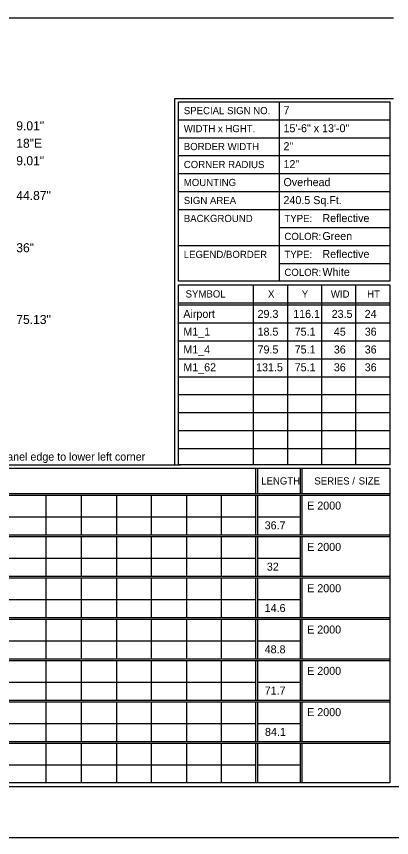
# Model space of a CAD drawing. Extents: x 2149934 to 2150188, y 145114 to 145238.
# Drawn here: x 2150052 to 2150076.2, y 145114.1 to 145167.1 of the extents above; entities that cross this region are included whole.
import ezdxf

# ---------------------------------------------------------------- set-up
doc = ezdxf.new("R2010")
doc.units = 0
for name, color, linetype in [('BORDER', 7, 'Continuous'), ('GSDIMS', 7, 'Continuous'), ('GSSHT', 7, 'Continuous'), ('Level 1', 7, 'Continuous'), ('PDF', 7, 'Continuous')]:
    doc.layers.add(name, color=color, linetype=linetype)

msp = doc.modelspace()

# ---------------------------------------------------------------- linework, layer by layer
at = {"layer": 'BORDER'}
for p, q in [((2150017.557, 145117.388), (2150171.536, 145117.388)), ((2150010.458, 145114.088), (2150174.061, 145114.088))]:
    msp.add_line(p, q, dxfattribs=at)
at = {"layer": 'Level 1'}
for p, q in [((2150076.316, 145166.95), (2150017.557, 145166.95)), ((2150062.21, 145161.778), (2150076.316, 145161.778)), ((2150068.935, 145161.546), (2150068.935, 145149.975)), ((2150062.442, 145160.387), (2150076.084, 145160.387)), ((2150062.442, 145159.227), (2150076.084, 145159.227)), ((2150062.442, 145158.091), (2150076.084, 145158.091)), ((2150062.442, 145156.932), (2150076.084, 145156.932)), ((2150062.442, 145155.772), (2150076.084, 145155.772)), ((2150062.442, 145154.613), (2150076.084, 145154.613)), ((2150068.935, 145153.453), (2150076.084, 145153.453)), ((2150062.442, 145152.294), (2150076.084, 145152.294)), ((2150068.935, 145151.134), (2150076.084, 145151.134)), ((2150062.442, 145138.143), (2150062.442, 145149.743)), ((2150062.442, 145149.743), (2150076.084, 145149.743)), ((2150067.272, 145149.737), (2150067.272, 145148.578)), ((2150069.475, 145149.737), (2150069.475, 145148.578)), ((2150071.678, 145149.737), (2150071.678, 145148.578)), ((2150073.881, 145149.737), (2150073.881, 145148.578)), ((2150076.084, 145149.743), (2150076.084, 145138.143)), ((2150062.442, 145148.578), (2150076.084, 145148.578)), ((2150062.442, 145148.462), (2150076.084, 145148.462)), ((2150067.272, 145148.578), (2150067.272, 145138.143)), ((2150069.475, 145148.578), (2150069.475, 145138.143)), ((2150071.678, 145148.578), (2150071.678, 145138.143)), ((2150073.881, 145148.578), (2150073.881, 145138.143)), ((2150062.442, 145147.303), (2150076.084, 145147.303)), ((2150062.442, 145146.143), (2150076.084, 145146.143)), ((2150062.442, 145144.984), (2150076.084, 145144.984)), ((2150062.442, 145143.824), (2150076.084, 145143.824)), ((2150062.442, 145142.665), (2150076.084, 145142.665)), ((2150062.442, 145141.505), (2150076.084, 145141.505)), ((2150062.442, 145140.346), (2150076.084, 145140.346)), ((2150062.442, 145139.186), (2150076.084, 145139.186)), ((2150017.557, 145138.143), (2150062.583, 145138.143)), ((2150076.084, 145138.143), (2150062.442, 145138.143)), ((2150067.426, 145137.911), (2150067.426, 145136.288)), ((2150067.542, 145137.911), (2150067.542, 145136.288)), ((2150070.29, 145137.911), (2150070.29, 145136.288)), ((2150070.405, 145137.911), (2150070.405, 145136.288)), ((2150017.789, 145136.288), (2150076.084, 145136.288)), ((2150017.789, 145136.172), (2150076.084, 145136.172)), ((2150053.895, 145136.172), (2150053.895, 145133.621)), ((2150056.168, 145136.172), (2150056.168, 145133.621)), ((2150058.441, 145136.172), (2150058.441, 145133.621)), ((2150060.69, 145136.172), (2150060.69, 145133.621)), ((2150062.962, 145136.172), (2150062.962, 145133.621)), ((2150065.212, 145136.172), (2150065.212, 145133.621)), ((2150067.426, 145136.172), (2150067.426, 145133.621)), ((2150067.542, 145136.172), (2150067.542, 145133.621)), ((2150070.29, 145136.172), (2150070.29, 145133.621)), ((2150070.405, 145136.172), (2150070.405, 145133.621)), ((2150017.789, 145134.78), (2150067.426, 145134.78)), ((2150067.542, 145134.78), (2150070.29, 145134.78)), ((2150017.789, 145133.621), (2150076.084, 145133.621)), ((2150017.789, 145133.505), (2150076.084, 145133.505)), ((2150053.895, 145133.505), (2150053.895, 145130.954)), ((2150056.168, 145133.505), (2150056.168, 145130.954)), ((2150058.441, 145133.505), (2150058.441, 145130.954)), ((2150060.69, 145133.505), (2150060.69, 145130.954)), ((2150062.962, 145133.505), (2150062.962, 145130.954)), ((2150065.212, 145133.505), (2150065.212, 145130.954)), ((2150067.426, 145133.505), (2150067.426, 145130.954)), ((2150067.542, 145133.505), (2150067.542, 145130.954)), ((2150070.29, 145133.505), (2150070.29, 145130.954)), ((2150070.405, 145133.505), (2150070.405, 145130.954)), ((2150017.789, 145132.113), (2150067.426, 145132.113)), ((2150067.542, 145132.113), (2150070.29, 145132.113)), ((2150017.789, 145130.954), (2150076.084, 145130.954)), ((2150017.789, 145130.838), (2150076.084, 145130.838)), ((2150053.895, 145130.838), (2150053.895, 145128.287)), ((2150056.168, 145130.838), (2150056.168, 145128.287)), ((2150058.441, 145130.838), (2150058.441, 145128.287)), ((2150060.69, 145130.838), (2150060.69, 145128.287)), ((2150062.962, 145130.838), (2150062.962, 145128.287)), ((2150065.212, 145130.838), (2150065.212, 145128.287)), ((2150067.426, 145130.838), (2150067.426, 145128.287)), ((2150067.542, 145130.838), (2150067.542, 145128.287)), ((2150070.29, 145130.838), (2150070.29, 145128.287)), ((2150070.405, 145130.838), (2150070.405, 145128.287)), ((2150017.789, 145129.447), (2150067.426, 145129.447)), ((2150067.542, 145129.447), (2150070.29, 145129.447)), ((2150017.789, 145128.287), (2150076.084, 145128.287)), ((2150017.789, 145128.171), (2150076.084, 145128.171)), ((2150053.895, 145128.171), (2150053.895, 145125.62)), ((2150056.168, 145128.171), (2150056.168, 145125.62)), ((2150058.441, 145128.171), (2150058.441, 145125.62)), ((2150060.69, 145128.171), (2150060.69, 145125.62)), ((2150062.962, 145128.171), (2150062.962, 145125.62)), ((2150065.212, 145128.171), (2150065.212, 145125.62)), ((2150067.426, 145128.171), (2150067.426, 145125.62)), ((2150067.542, 145128.171), (2150067.542, 145125.62)), ((2150070.29, 145128.171), (2150070.29, 145125.62)), ((2150070.405, 145128.171), (2150070.405, 145125.62)), ((2150017.789, 145126.78), (2150067.426, 145126.78)), ((2150067.542, 145126.78), (2150070.29, 145126.78)), ((2150017.789, 145125.62), (2150076.084, 145125.62)), ((2150017.789, 145125.504), (2150076.084, 145125.504)), ((2150053.895, 145125.504), (2150053.895, 145122.954)), ((2150056.168, 145125.504), (2150056.168, 145122.954)), ((2150058.441, 145125.504), (2150058.441, 145122.954)), ((2150060.69, 145125.504), (2150060.69, 145122.954)), ((2150062.962, 145125.504), (2150062.962, 145122.954)), ((2150065.212, 145125.504), (2150065.212, 145122.954)), ((2150067.426, 145125.504), (2150067.426, 145122.954)), ((2150067.542, 145125.504), (2150067.542, 145122.954)), ((2150070.29, 145125.504), (2150070.29, 145122.954)), ((2150070.405, 145125.504), (2150070.405, 145122.954)), ((2150017.789, 145124.113), (2150067.426, 145124.113)), ((2150067.542, 145124.113), (2150070.29, 145124.113)), ((2150017.789, 145122.954), (2150076.084, 145122.954)), ((2150017.789, 145122.838), (2150076.084, 145122.838)), ((2150053.895, 145122.838), (2150053.895, 145120.287)), ((2150056.168, 145122.838), (2150056.168, 145120.287)), ((2150058.441, 145122.838), (2150058.441, 145120.287)), ((2150060.69, 145122.838), (2150060.69, 145120.287)), ((2150062.962, 145122.838), (2150062.962, 145120.287)), ((2150065.212, 145122.838), (2150065.212, 145120.287)), ((2150067.426, 145122.838), (2150067.426, 145120.287)), ((2150067.542, 145122.838), (2150067.542, 145120.287)), ((2150070.29, 145122.838), (2150070.29, 145120.287)), ((2150070.405, 145122.838), (2150070.405, 145120.287)), ((2150017.789, 145121.446), (2150067.426, 145121.446)), ((2150067.542, 145121.446), (2150070.29, 145121.446)), ((2150017.789, 145120.287), (2150076.084, 145120.287)), ((2150017.789, 145120.171), (2150076.084, 145120.171)), ((2150053.895, 145120.171), (2150053.895, 145117.62)), ((2150056.168, 145120.171), (2150056.168, 145117.62)), ((2150058.441, 145120.171), (2150058.441, 145117.62)), ((2150060.69, 145120.171), (2150060.69, 145117.62)), ((2150062.962, 145120.171), (2150062.962, 145117.62)), ((2150065.212, 145120.171), (2150065.212, 145117.62)), ((2150067.426, 145120.171), (2150067.426, 145117.62)), ((2150067.542, 145120.171), (2150067.542, 145117.62)), ((2150070.29, 145120.171), (2150070.29, 145117.62)), ((2150070.405, 145120.171), (2150070.405, 145117.62)), ((2150017.789, 145118.779), (2150067.426, 145118.779)), ((2150067.542, 145118.779), (2150070.29, 145118.779))]:
    msp.add_line(p, q, dxfattribs=at)
msp.add_lwpolyline([(2150062.21, 145138.143), (2150062.21, 145161.778)], dxfattribs=at)
for points in [[(2150062.442, 145161.546), (2150076.084, 145161.546), (2150076.084, 145149.975), (2150062.442, 145149.975)], [(2150017.789, 145137.911), (2150076.084, 145137.911), (2150076.084, 145117.62), (2150017.789, 145117.62)]]:
    msp.add_lwpolyline(points, close=True, dxfattribs=at)
at = {"layer": 'PDF'}
msp.add_lwpolyline([(2150010.458, 145114.088), (2150174.061, 145114.088), (2150174.061, 145219.948), (2150010.458, 145219.948)], close=True, dxfattribs=at)

# ---------------------------------------------------------------- texts
at = {"layer": 'GSDIMS'}
for s, p in [('9.01"', (2150051.978, 145159.717)), ('18"E', (2150051.978, 145158.592)), ('9.01"', (2150051.978, 145157.466)), ('44.87"', (2150051.978, 145155.221)), ('36"', (2150051.978, 145151.852)), ('75.13"', (2150051.978, 145147.221))]:
    msp.add_text(s, height=0.5833, dxfattribs=at).set_placement(p)
at = {"layer": 'GSSHT'}
for s, height, p in [('7', 0.517, (2150069.224, 145160.753)), ('Overhead', 0.5165, (2150069.224, 145156.117))]:
    msp.add_text(s, height=height, dxfattribs=at).set_placement(p)
at = {"layer": 'Level 1'}
for s, height, p in [('SPECIAL SIGN NO.', 0.46374, (2150062.79, 145160.758)), ('WIDTH x HGHT.', 0.46374, (2150062.79, 145159.598)), ('15\'-6" x 13\'-0"', 0.51652, (2150069.224, 145159.594)), ('BORDER WIDTH', 0.46374, (2150062.79, 145158.439)), ('2"', 0.5165, (2150069.224, 145158.435)), ('CORNER RADIUS', 0.46374, (2150062.79, 145157.28)), ('12"', 0.5165, (2150069.224, 145157.276)), ('MOUNTING', 0.4637, (2150062.79, 145156.12)), ('SIGN AREA', 0.4638, (2150062.79, 145154.961)), ('240.5 Sq.Ft.', 0.51652, (2150069.224, 145154.958)), ('BACKGROUND', 0.4637, (2150062.79, 145153.801)), ('TYPE:', 0.4637, (2150069.283, 145153.801)), ('Reflective', 0.5165, (2150071.736, 145153.799)), ('COLOR:', 0.4637, (2150069.283, 145152.642)), ('Green', 0.5165, (2150071.736, 145152.64)), ('LEGEND/BORDER', 0.46374, (2150062.79, 145151.482)), ('TYPE:', 0.4637, (2150069.283, 145151.482)), ('Reflective', 0.5165, (2150071.736, 145151.482)), ('White', 0.5165, (2150071.736, 145150.323)), ('COLOR:', 0.4637, (2150069.283, 145150.323)), ('SYMBOL', 0.4637, (2150062.906, 145148.931)), ('X', 0.464, (2150068.223, 145148.926)), ('Y', 0.464, (2150070.403, 145148.926)), ('WID', 0.4637, (2150072.281, 145148.926)), ('HT', 0.4637, (2150074.623, 145148.926)), ('Airport', 0.5165, (2150062.761, 145147.615)), ('29.3', 0.5165, (2150067.551, 145147.615)), ('116.1', 0.5165, (2150069.851, 145147.615)), ('23.5', 0.5165, (2150072.333, 145147.615)), ('24', 0.5165, (2150074.464, 145147.615)), ('M1_1', 0.5165, (2150062.761, 145146.468)), ('18.5', 0.5165, (2150067.551, 145146.468)), ('75.1', 0.5165, (2150069.946, 145146.468)), ('45', 0.5165, (2150072.474, 145146.468)), ('36', 0.5165, (2150074.467, 145146.468)), ('M1_4', 0.5165, (2150062.761, 145145.32)), ('79.5', 0.5165, (2150067.551, 145145.32)), ('75.1', 0.5165, (2150069.946, 145145.32)), ('36', 0.5165, (2150072.474, 145145.32)), ('36', 0.5165, (2150074.467, 145145.32)), ('M1_62', 0.5165, (2150062.761, 145144.172)), ('131.5', 0.5165, (2150067.457, 145144.172)), ('75.1', 0.5165, (2150069.946, 145144.172)), ('36', 0.5165, (2150072.474, 145144.172)), ('36', 0.5165, (2150074.467, 145144.172)), ('Letter locations are panel edge to lower left corner', 0.51652, (2150044.943, 145138.406)), ('LENGTH', 0.4638, (2150067.783, 145136.867)), ('LENGTH', 0.4638, (2150067.783, 145136.867)), ('SERIES /', 0.4638, (2150071.216, 145136.867)), ('SIZE', 0.4638, (2150074.074, 145136.867)), ('E 2000', 0.5165, (2150070.753, 145135.248)), ('36.7', 0.5165, (2150068.009, 145133.973)), ('E 2000', 0.5165, (2150070.753, 145132.583)), ('32', 0.5165, (2150068.15, 145131.308)), ('E 2000', 0.5165, (2150070.753, 145129.917)), ('14.6', 0.5165, (2150068.009, 145128.642)), ('E 2000', 0.5165, (2150070.753, 145127.252)), ('48.8', 0.5165, (2150068.009, 145125.977)), ('E 2000', 0.5165, (2150070.753, 145124.586)), ('71.7', 0.5165, (2150068.009, 145123.311)), ('E 2000', 0.5165, (2150070.753, 145121.921)), ('84.1', 0.5165, (2150068.03, 145120.646))]:
    msp.add_text(s, height=height, dxfattribs=at).set_placement(p)

doc.saveas('drawing.dxf')
